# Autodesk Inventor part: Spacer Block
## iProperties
Shininess: 64.0
Length Units: 11272
Angle Units: 11279
Time Units: 11290
Mass Units: 11286
Length Display Precision: 3
Angle Display Precision: 2
Compacted: True
Part Number: Spacer Block
Document SubType Name: Modeling
Created: 2003-08
Designer: FT User
Manufacturer: Standard
Standards Organization: Custom
Density: 0.0
Volumn: 0.0
Area: 0.0
PropertySet Name: Model Information
Control State: 0
Master: False
Checked Out: False
Author: FT User
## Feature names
1. Extrusion1
2. Hole1
3. Hole2
